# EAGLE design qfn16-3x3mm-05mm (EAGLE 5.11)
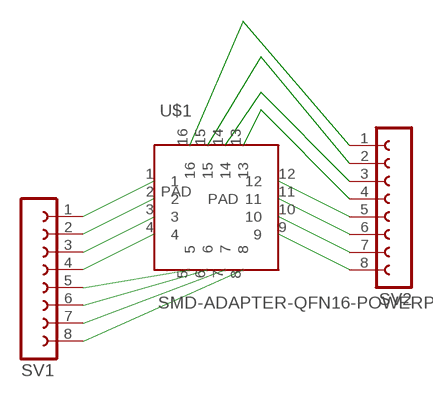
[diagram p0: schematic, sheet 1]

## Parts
SV1  FE08-1  [FE08]
SV2  FE08-1  [FE08]
U$1  SMD-ADAPTER-QFN16-POWERPAD  [QFN16-3X3-0.5PITCH]

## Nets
N$1: SV1.1 U$1.1
N$2: SV1.2 U$1.2
N$3: SV1.3 U$1.3
N$4: SV1.4 U$1.4
N$5: SV1.5 U$1.5
N$6: SV1.6 U$1.6
N$7: SV1.7 U$1.7
N$8: SV1.8 U$1.8
N$9: SV2.8 U$1.9
N$10: SV2.7 U$1.10
N$11: SV2.6 U$1.11
N$12: SV2.5 U$1.12
N$13: SV2.4 U$1.13
N$14: SV2.3 U$1.14
N$15: SV2.2 U$1.15
N$16: SV2.1 U$1.16
Unconnected: U$1.PAD

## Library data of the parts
SV1 SV2 = con-lsta:FE08-1: FEMALE HEADER; OC_FARNELL: unknown; OC_NEWARK: unknown
U$1 = trl:SMD-ADAPTER-QFN16-POWERPAD

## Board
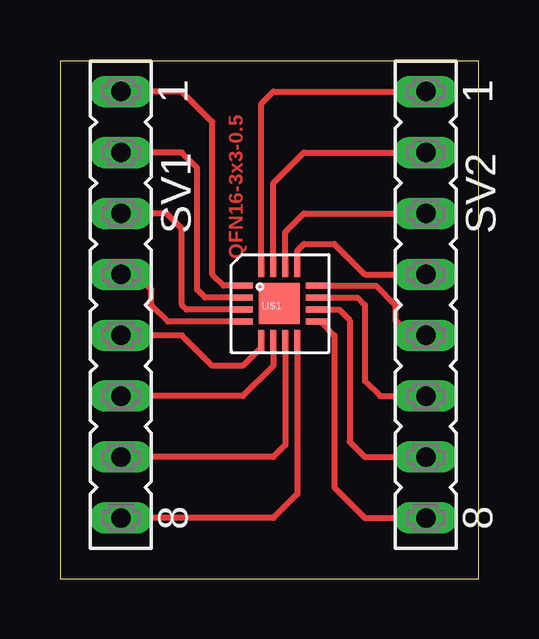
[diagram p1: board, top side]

Size 17.45 x 21.58 mm. Coordinates in mm from the lower left corner, seen from the top.
Outline: 0,0 17.45,0 17.45,21.58 0,21.58 0,0
Copper layers (1*16): Top 0.035mm / dielectric 1.5mm / Bottom 0.035mm
Design rules "default": minimum track width 10mil, minimum drill 24mil, track to track 8mil, track to pad 8mil, pad to pad 8mil, via to via 8mil, smd to smd 8mil, copper to edge 40mil, drill to drill 8mil, minimum pad ring 10mil, minimum via ring 8mil, stop-mask expansion 4mil, vias tented up to drill 0mil, thermal gap 10mil

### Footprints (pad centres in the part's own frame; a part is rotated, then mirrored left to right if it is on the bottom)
FE08 = drill 0.813 long: 1 -8.89,0; 2 -6.35,0; 3 -3.81,0; 4 -1.27,0; 5 1.27,0; 6 3.81,0; 7 6.35,0; 8 8.89,0
QFN16-3X3-0.5PITCH = smd 0.9 x 0.25: 1 -1.3,0.8; 2 -1.3,0.3; 3 -1.3,-0.2; 4 -1.3,-0.7; 9 1.8,-0.7; 10 1.8,-0.2; 11 1.8,0.3; 12 1.8,0.8 | smd 0.25 x 0.9: 5 -0.5,-1.5; 6 0,-1.5; 7 0.5,-1.5; 8 1,-1.5; 13 1,1.6; 14 0.5,1.6; 15 0,1.6; 16 -0.5,1.6 | smd 1.7 x 1.7: PAD 0.25,0.05

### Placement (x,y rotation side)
SV1  2.54,11.43 270 top
SV2  15.24,11.43 270 top
U$1  8.89,11.43 0 top

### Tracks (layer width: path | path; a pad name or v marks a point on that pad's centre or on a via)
N$1
  Top 0.254: U$1.1 6.82,12.23 6.35,12.7 6.35,19.05 5.08,20.32 SV1.1
N$2
  Top 0.254: U$1.2 6.05,11.73 5.71,12.06 5.71,17.14 5.08,17.78 SV1.2
N$3
  Top 0.254: U$1.3 5.28,11.23 5.08,11.43 5.08,14.61 4.45,15.24 SV1.3
N$4
  Top 0.254: U$1.4 4.51,10.73 3.81,11.43 3.81,12.06 3.17,12.7 SV1.4
N$5
  Top 0.254: U$1.5 8.39,9.66 7.62,8.89 6.35,8.89 5.08,10.16 SV1.5
N$6
  Top 0.254: U$1.6 8.89,8.89 7.62,7.62 SV1.6
N$7
  Top 0.254: U$1.7 9.39,5.58 8.89,5.08 SV1.7
N$8
  Top 0.254: U$1.8 9.89,3.54 8.89,2.54 SV1.8
N$9
  Top 0.254: U$1.9 10.86,10.73 11.43,10.16 11.43,3.81 12.7,2.54 SV2.8
N$10
  Top 0.254: U$1.10 11.63,11.23 12.06,10.79 12.06,5.71 12.7,5.08 SV2.7
N$11
  Top 0.254: U$1.11 12.4,11.73 12.7,11.43 12.7,8.26 13.34,7.62 SV2.6
N$12
  Top 0.254: U$1.12 13.17,12.23 13.97,11.43 13.97,10.79 14.61,10.16 SV2.5
N$13
  Top 0.254: U$1.13 9.89,13.7 10.16,13.97 11.43,13.97 12.7,12.7 SV2.4
N$14
  Top 0.254: U$1.14 9.39,14.47 10.16,15.24 SV2.3
N$15
  Top 0.254: U$1.15 8.89,16.51 10.16,17.78 SV2.2
N$16
  Top 0.254: U$1.16 8.39,19.82 8.89,20.32 SV2.1

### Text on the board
Top: QFN16-3x3-0.5
_tPlace: U$1
_tNames: SV1 | SV2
